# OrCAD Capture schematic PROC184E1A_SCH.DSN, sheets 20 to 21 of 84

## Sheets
20 20. SOC GENERAL & USB: size C; title: GENERAL IO; company: TEXAS INSTRUMENTS INCORPORATED; note: PROC184_SCH
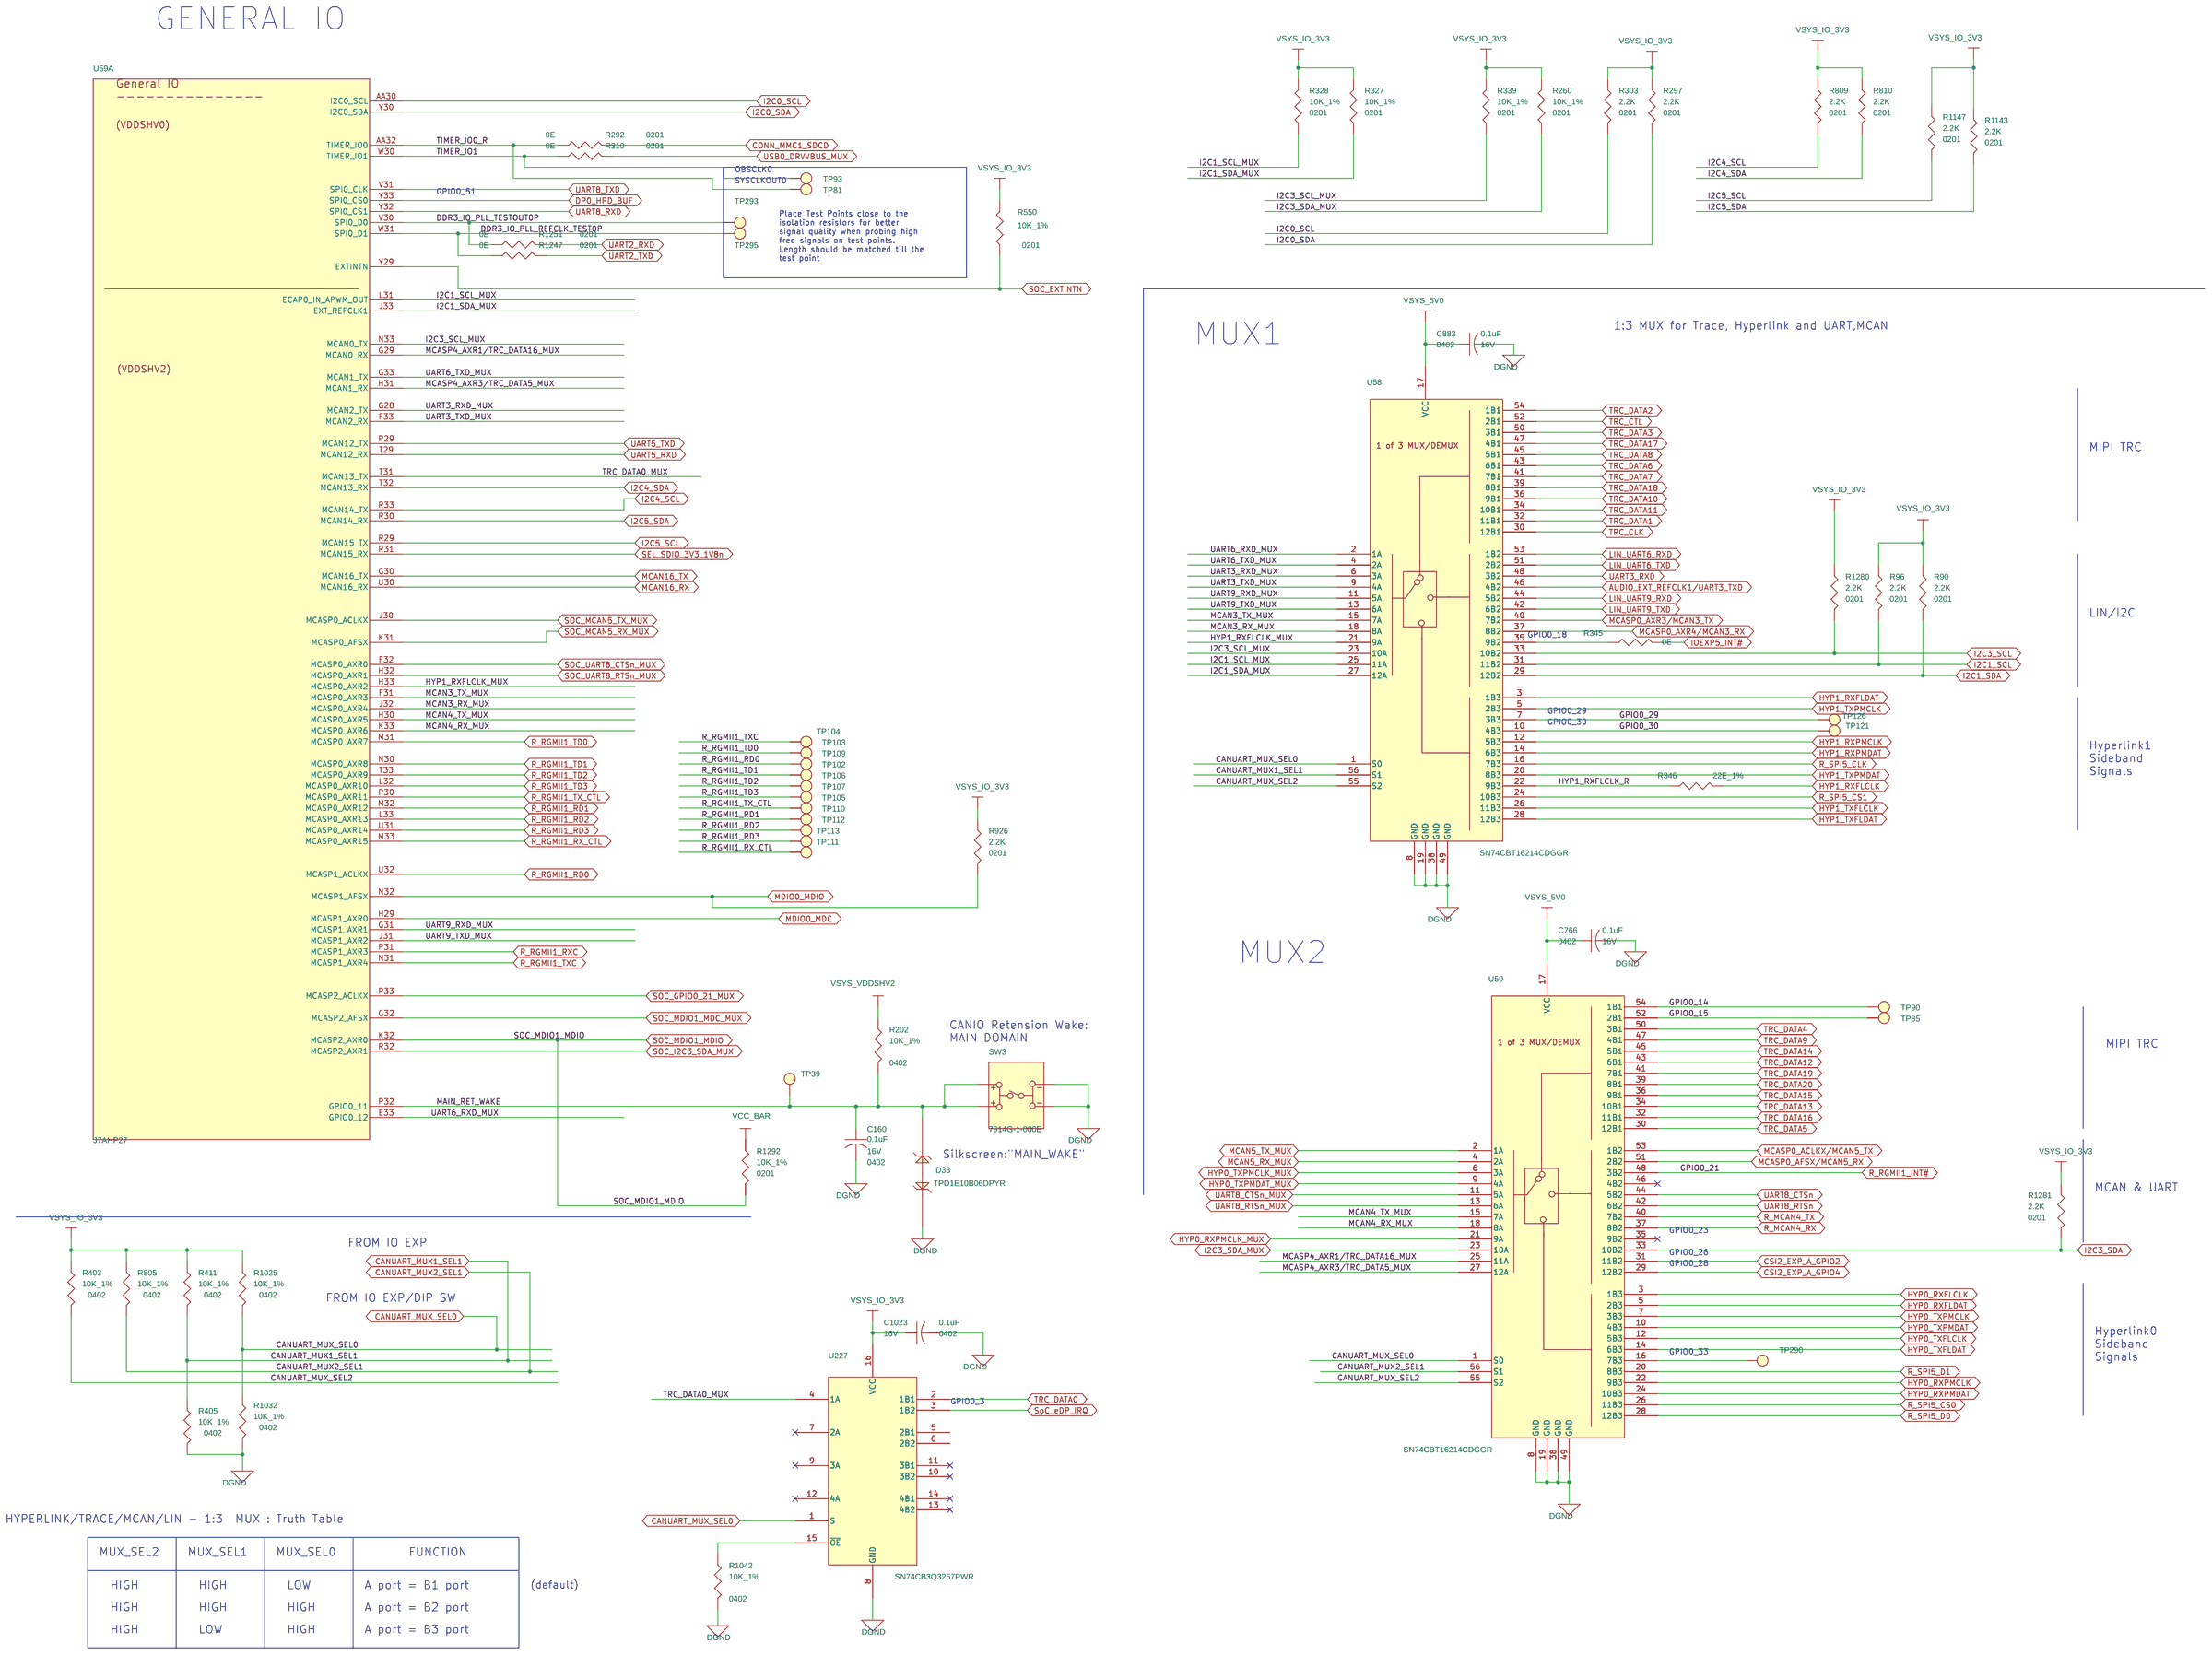
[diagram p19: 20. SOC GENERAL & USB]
21 21. SOC MCU & MMC & ADCs: size C; title: MCU RGMII & ADC; company: TEXAS INSTRUMENTS INCORPORATED; note: PROC184_SCH
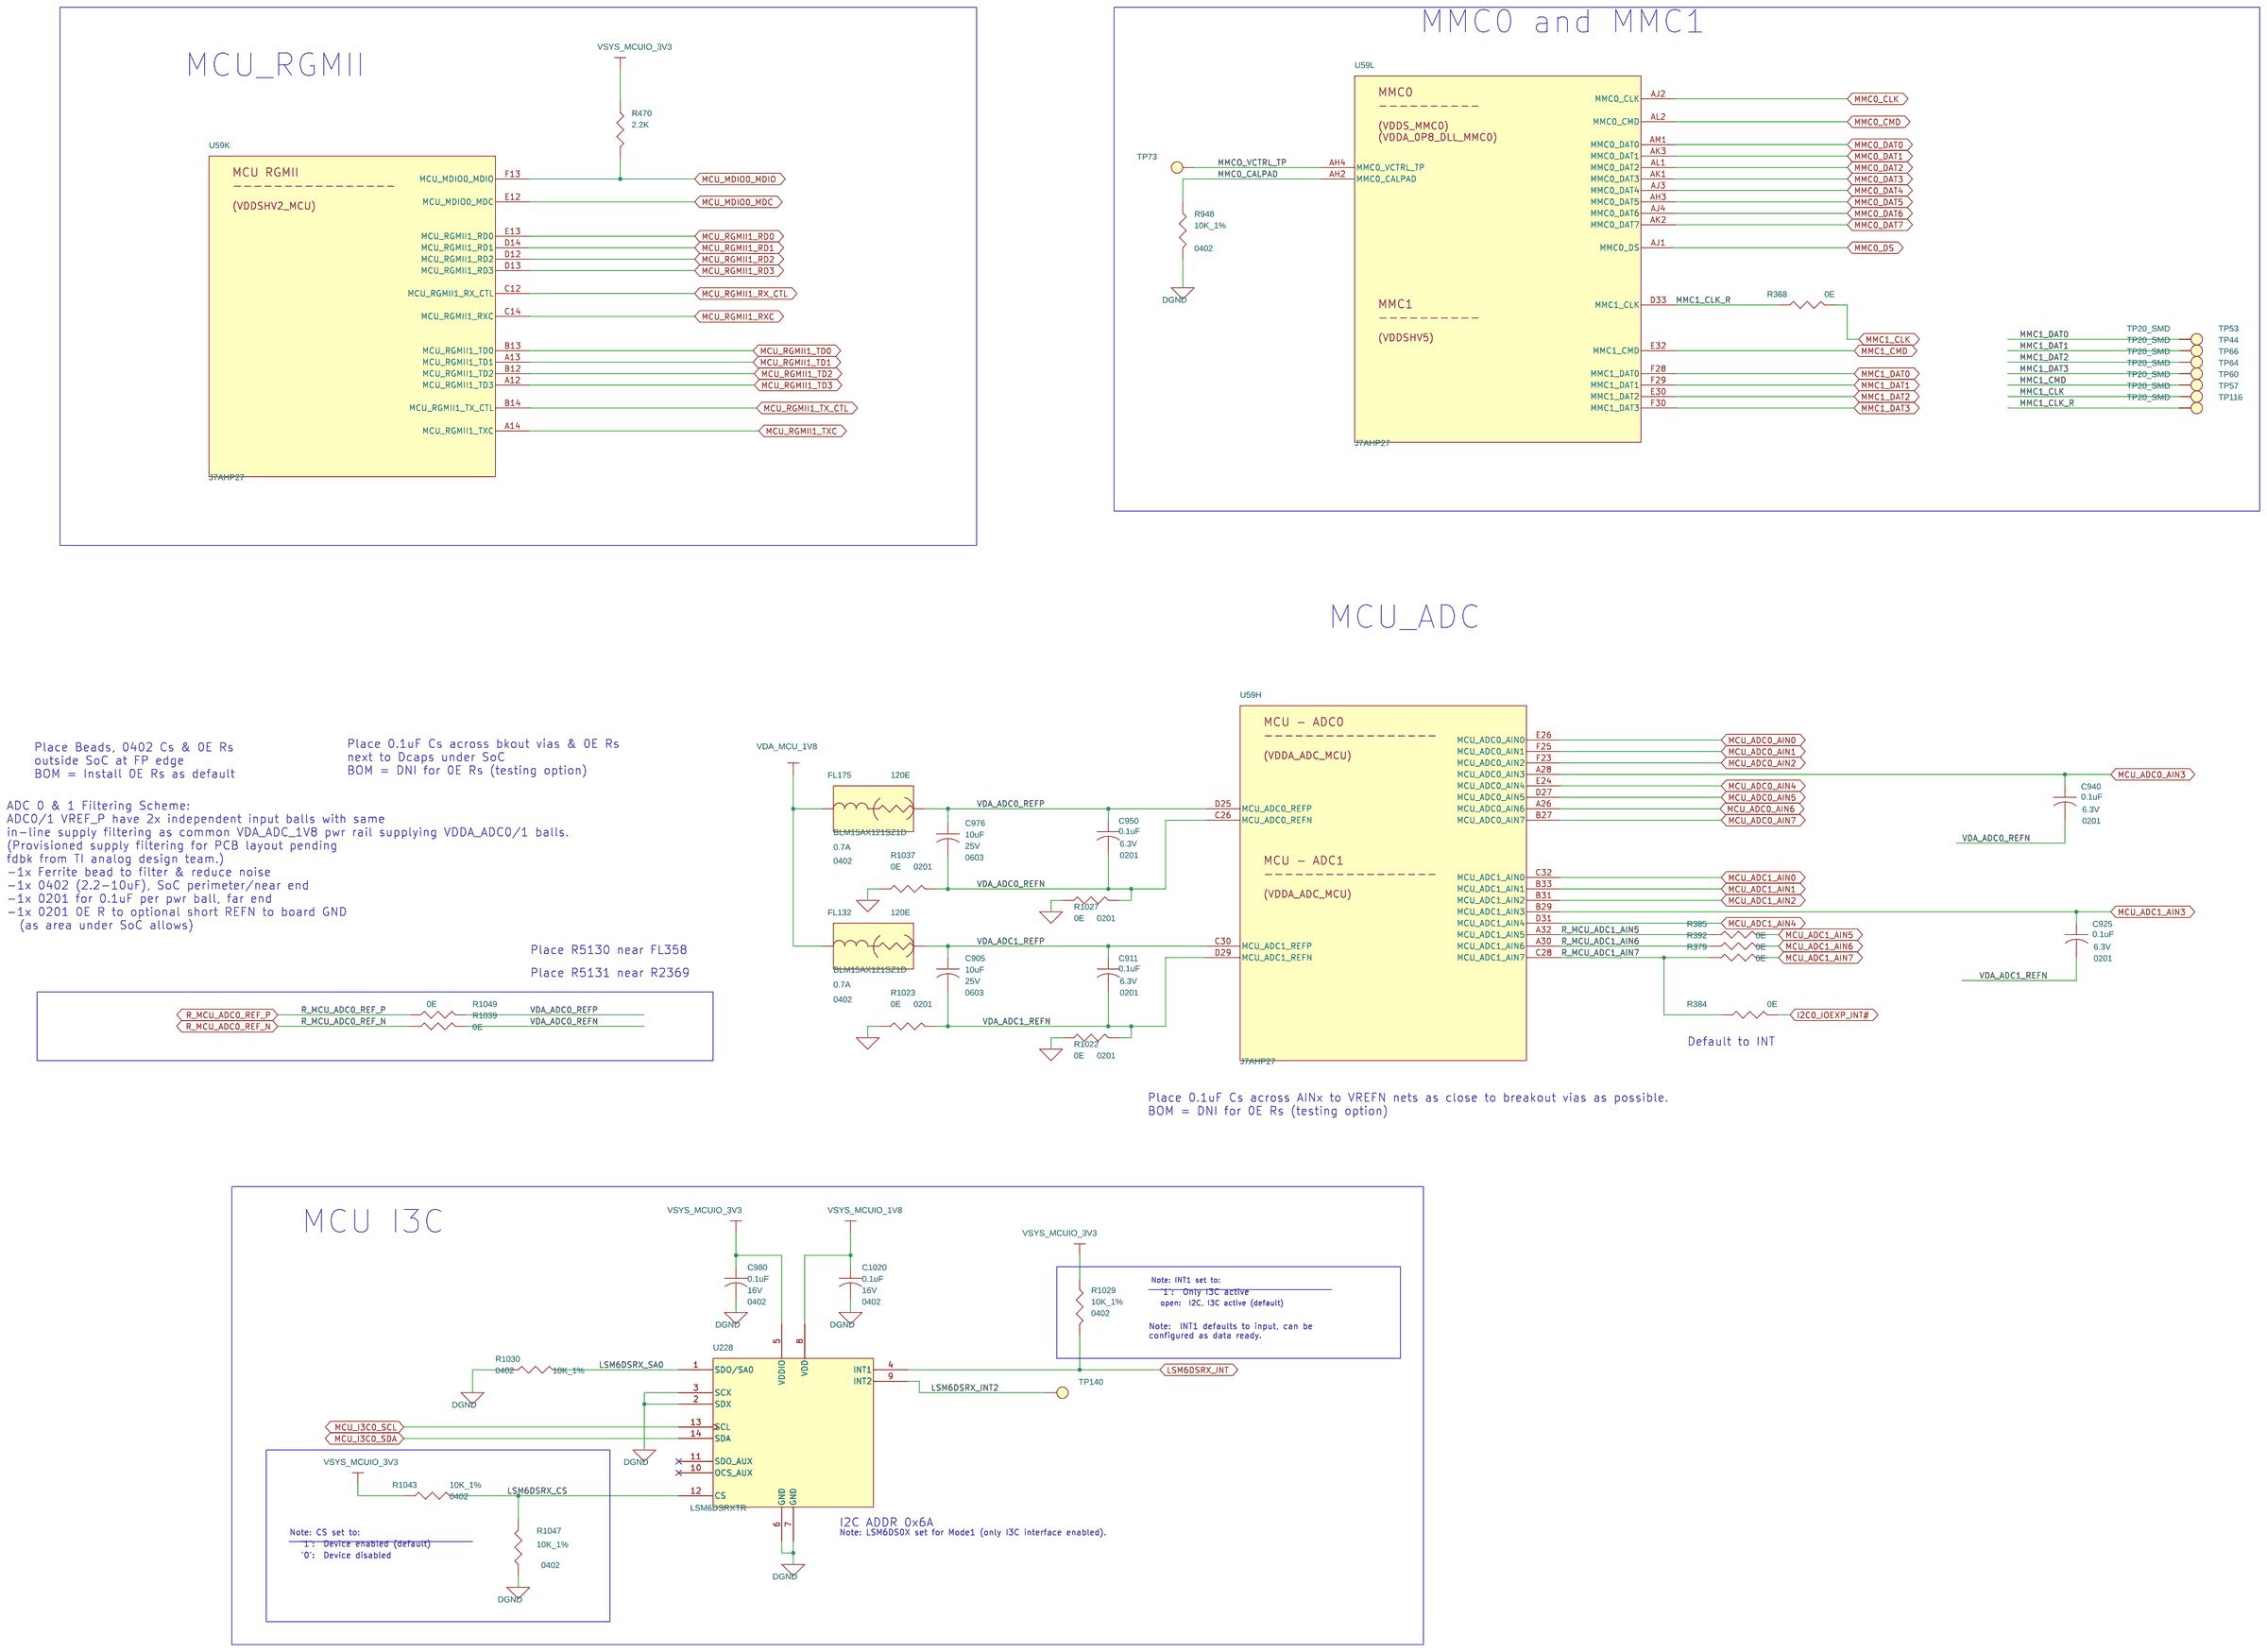
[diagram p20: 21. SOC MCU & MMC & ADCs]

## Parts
sheet 15. SOC EMIF1 & LPDDR4
U59  J7AHP27  [BGASKT-33X33-1063-P8MM]  (sections A,B,C,D,E,F,G,H,I,J,K,L,M,N,O,P,Q,R,S,T,U,V,W)
sheet 20. SOC GENERAL & USB
C160  0.1uF  [CAP0402_0-75]
C766  0.1uF  [CAP0402_0-75]
C883  0.1uF  [CAP0402_0-75]
C1023  0.1uF  [CAP0402_0-75]
D33  TPD1E10B06DPYR  [DIO_DFN0402_0-5]
R90  2.2K  [RES0201_0-5]
R96  2.2K  [RES0201_0-5]
R202  10K_1%  [RES0402_0-5]
R260  10K_1%  [RES0201_0-5]
R292  0E  [RES0201_0-5]
R297  2.2K  [RES0201_0-5]
R303  2.2K  [RES0201_0-5]
R310  0E  [RES0201_0-5]
R327  10K_1%  [RES0201_0-5]
R328  10K_1%  [RES0201_0-5]
R339  10K_1%  [RES0201_0-5]
R345  0E  [RES0201_0-5]
R346  22E_1%  [RES0402_0-5]
R403  10K_1%  [RES0402_0-5]
R405  10K_1%  [RES0402_0-5]
R411  10K_1%  [RES0402_0-5]
R550  10K_1%  [RES0201_0-5]
R805  10K_1%  [RES0402_0-5]
R809  2.2K  [RES0201_0-5]
R810  2.2K  [RES0201_0-5]
R926  2.2K  [RES0201_0-5]
R1025  10K_1%  [RES0402_0-5]
R1032  10K_1%  [RES0402_0-5]
R1042  10K_1%  [RES0402_0-5]
R1143  2.2K  [RES0201_0-5]
R1147  2.2K  [RES0201_0-5]
R1247  0E  [RES0201_0-5]
R1251  0E  [RES0201_0-5]
R1280  2.2K  [RES0201_0-5]
R1281  2.2K  [RES0201_0-5]
R1292  10K_1%  [RES0201_0-5]
SW3  7914G-1-000E  [SW4_100X216_200X200_SMD_4-2]
TP39  TP30_SMD  [TP30_SMD]
TP81  TP30_SMD  [TP30_SMD]
TP85  TP30_SMD  [TP30_SMD]
TP90  TP30_SMD  [TP30_SMD]
TP93  TP30_SMD  [TP30_SMD]
TP102  TP20_SMD  [TP20_SMD]
TP103  TP20_SMD  [TP20_SMD]
TP104  TP20_SMD  [TP20_SMD]
TP105  TP20_SMD  [TP20_SMD]
TP106  TP20_SMD  [TP20_SMD]
TP107  TP20_SMD  [TP20_SMD]
TP109  TP20_SMD  [TP20_SMD]
TP110  TP20_SMD  [TP20_SMD]
TP111  TP20_SMD  [TP20_SMD]
TP112  TP20_SMD  [TP20_SMD]
TP113  TP20_SMD  [TP20_SMD]
TP121  TP30_SMD  [TP30_SMD]
TP126  TP30_SMD  [TP30_SMD]
TP290  TP30_SMD  [TP30_SMD]
TP293  TP30_SMD  [TP30_SMD]
TP295  TP30_SMD  [TP30_SMD]
U50  SN74CBT16214CDGGR  [TSSOP56_19-68_560X240_1-2]
U58  SN74CBT16214CDGGR  [TSSOP56_19-68_560X240_1-2]
U227  SN74CB3Q3257PWR  [TSSOP16_25-59_205X180]
sheet 21. SOC MCU & MMC & ADCs
C905  10uF  [CAP0603_1-25]
C911  0.1uF  [CAP0201_0-5]
C925  0.1uF  [CAP0201_0-5]
C940  0.1uF  [CAP0201_0-5]
C950  0.1uF  [CAP0201_0-5]
C976  10uF  [CAP0603_1-25]
C980  0.1uF  [CAP0402_0-75]
C1020  0.1uF  [CAP0402_0-75]
FL132  120E  [EMIFIL_BLM15A_0402_0-6]
FL175  120E  [EMIFIL_BLM15A_0402_0-6]
R368  0E  [RES0402_0-5]
R379  0E  [RES0402_0-5]
R384  0E  [RES0402_0-5]
R385  0E  [RES0402_0-5]
R392  0E  [RES0402_0-5]
R470  2.2K  [RES0201_0-5]
R948  10K_1%  [RES0402_0-5]
R1022  0E  [RES0201_0-5]
R1023  0E  [RES0201_0-5]
R1027  0E  [RES0201_0-5]
R1029  10K_1%  [RES0402_0-5]
R1030  10K_1%  [RES0402_0-5]
R1037  0E  [RES0201_0-5]
R1039  0E  [RES0201_0-5]
R1043  10K_1%  [RES0402_0-5]
R1047  10K_1%  [RES0402_0-5]
R1049  0E  [RES0201_0-5]
TP44  TP20_SMD  [TP20_SMD]
TP53  TP20_SMD  [TP20_SMD]
TP57  TP20_SMD  [TP20_SMD]
TP60  TP20_SMD  [TP20_SMD]
TP64  TP20_SMD  [TP20_SMD]
TP66  TP20_SMD  [TP20_SMD]
TP73  TP30_SMD  [TP30_SMD]
TP116  TP20_SMD  [TP20_SMD]
TP140  TP30_SMD  [TP30_SMD]
U228  LSM6DSRXTR  [LGA14_19-68_120X100_0-9]

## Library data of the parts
U59 = J7AHP27SoC_BGA1063: IC J7AHP27 SoC EVM MICROPROCESSOR BGA1063; Chkd/date: PRADEEP/181223; Crtd /date: TAMILARASU/111223; Custom_Duty: 15%; Customs_HS_Code: 85423100; Distributor_name: NA; Distributor_part_number: NA; Footprint Path: Y:\MIS_DATABASE\Library\ALTIUM_TOOL\PCB_FOOTPRINTS\Altium_Footprint_Lib.PcbLib; Height: 3.30MM; Library Path: Y:\MIS_DATABASE\Library\ALTIUM_TOOL\SCHEMATICS_PARTS\MS_MICROPROCESSOR_Library.schlib; Mfr_name: NA; Mistral Part No: 141223120002; Package: BGA1063; Part_type: ICS\DIGITAL\MICROPROCESSOR; Project: J7AHP27_V08 SOC; RoHS: NA; Temperature: NA; Tolerance: NA; Voltage: NA; Wattage: NA; Weight: NA; Datasheet: Y:\MIS_DATABASE\DATASHEETS\ICS\DIGITAL\MICROCONTROLLER\J7AHP27.PDF
C160 C766 C883 C980 C1020 C1023 = CAP: CAP CERAMIC 0.1uF 16V 10% X7R AUTO 0402; Automotive Alternate_mfr_name: TDK; Automotive Alternate_mfr_part_number: CGA2B1X7R1C104K050BC; Chkd/date: NAVEED/021014; Crtd /date: VASANTHA/300514; Custom_Duty: 15%; Customs_HS_Code: 85322990; Direct Alternate_mfr_name: MURATA; Direct Alternate_mfr_part_number: GCM155R71C104JA55D; Distributor_name: DIGIKEY; Distributor_part_number: 490-4759-1-ND; Footprint Path: Y:\MIS_DATABASE\Library\ALTIUM_TOOL\PCB_FOOTPRINTS\Altium_Footprint_Lib.PcbLib; Height: 0.55MM; Library Path: Y:\MIS_DATABASE\Library\ALTIUM_TOOL\SCHEMATICS_PARTS\MS_DISCRETE_Library.schlib; Manufacturer: MURATA; Mfr_name: MURATA; Mfr_part_number: GCM155R71C104KA55D; Mistral Part No: 120016070006-R; Package: 0402; Part_type: CAPACITORS\CERAMIC; Project: DCMIST_FPGA_CARD; RoHS: RoHS; Temperature: -55°C+125°C; Tolerance: 10%; Voltage: 16V; Wattage: NA; Weight: 6mg; Datasheet: Y:\MIS_DATABASE\DATASHEETS\CAPACITORS\MURATA-GCM-SER.PDF
D33 = DIODE_SOD323: DIODE 1CH ESD PROTECTION X1SON2; Chkd/date: MANIRAJA/040420; Crtd /date: VASANTHA/181114; Custom_Duty: 15%; Customs_HS_Code: 85423100; Distributor_name: DIGIKEY; Distributor_part_number: 296-30406-1-ND; Footprint Path: Y:\MIS_DATABASE\Library\ALTIUM_TOOL\PCB_FOOTPRINTS\Altium_Footprint_Lib.PcbLib; Height: 0.45MM; Library Path: Y:\MIS_DATABASE\Library\ALTIUM_TOOL\SCHEMATICS_PARTS\MS_DISCRETE_Library.schlib; Manufacturer: TEXAS INSTRUMENTS; Mfr_name: TEXAS INSTRUMENTS; Mistral Part No: 130014110022-R; Package: X1SON2; Part_type: DIODE; Project: GALILEO_EVM; RoHS: RoHS; Temperature: -40°C+125°C; Tolerance: NA; Voltage: NA; Wattage: NA; Weight: 1mg; Datasheet: Y:\MIS_DATABASE\DATASHEETS\ICS\INTERFACE\TPD1E10B06-SER.PDF
R90 R96 R297 R303 R470 R809 R810 R926 R1143 R1147 R1280 R1281 = RESISTOR: RES 2.2K 1/20W 5% 0201; Chkd/date: MANIRAJA/050517; Crtd /date: MANIRAJA/050517; Custom_Duty: 15%; Customs_HS_Code: 85332119; Distributor_name: DIGIKEY; Distributor_part_number: 311-2.2KNCT-ND; Footprint Path: Y:\MIS_DATABASE\Library\ALTIUM_TOOL\PCB_FOOTPRINTS\Altium_Footprint_Lib.PcbLib; Height: 0.26MM; Library Path: Y:\MIS_DATABASE\Library\ALTIUM_TOOL\SCHEMATICS_PARTS\MS_DISCRETE_Library.schlib; Manufacturer: YAGEO AMERICA; Mfr_name: YAGEO AMERICA; Mfr_part_number: RC0201JR-072K2L; Mistral Part No: 110009030427-R; Package: 0201; Part_type: RESISTORS\FIXED; Project: GOLDEN-I LITE; RoHS: RoHS; Temperature: -55°C+125°C; Tolerance: 5%; Voltage: NA; Wattage: 1/20W; Weight: 0.17mg; Datasheet: Y:\MIS_DATABASE\DATASHEETS\RESISTORS\RCXXXXL-SER_MAR18.PDF
R202 = RESISTOR: RES 10K 1/16W 1% 0402; Assembly_Instruction: DNI; Chkd/date: VASANTHA/201216; Crtd /date: GEETHA/290506; Custom_Duty: 15%; Customs_HS_Code: 85332119; Distributor_name: DIGIKEY; Distributor_part_number: 311-10.0KLRTR-ND; Footprint Path: Y:\MIS_DATABASE\Library\ALTIUM_TOOL\PCB_FOOTPRINTS\Altium_Footprint_Lib.PcbLib; Height: 0.40MM; Library Path: Y:\MIS_DATABASE\Library\ALTIUM_TOOL\SCHEMATICS_PARTS\MS_DISCRETE_Library.schlib; Manufacturer: YAGEO AMERICA; Mfr_name: YAGEO AMERICA; Mfr_part_number: RC0402FR-0710KL; Mistral Part No: 110015090015-R; Package: 0402; Part_type: RESISTORS\FIXED; Project: VOCERA; RoHS: RoHS; Temperature: -55°C+155°C; Tolerance: 1%; Voltage: NA; Wattage: 1/16W; Weight: 0.65mg; Datasheet: Y:\MIS_DATABASE\DATASHEETS\RESISTORS\RCXXXXL-SER_MAR18.PDF
R260 R327 R328 R339 R550 = RESISTOR: RES 10K 1/20W 1% 0201; Chkd/date: MANIRAJA/080519; Crtd /date: ALVY/080519; Custom_Duty: 15%; Customs_HS_Code: 85332119; Distributor_name: DIGIKEY; Distributor_part_number: 1276-3670-1-ND; Footprint Path: Y:\MIS_DATABASE\Library\ALTIUM_TOOL\PCB_FOOTPRINTS\Altium_Footprint_Lib.PcbLib; Height: 0.26MM; Library Path: Y:\MIS_DATABASE\Library\ALTIUM_TOOL\SCHEMATICS_PARTS\MS_DISCRETE_Library.schlib; Manufacturer: SAMSUNG; Mfr_name: SAMSUNG; Mfr_part_number: RC0603F103CS; Mistral Part No: 110011040018-R; Package: 0201; Part_type: RESISTORS\FIXED; Project: BRUKER_SD820_COMMONDO; RoHS: RoHS; Temperature: -55°C+125°C; Tolerance: 1%; Voltage: NA; Wattage: 1/20W; Weight: 0.15mg; Datasheet: Y:\MIS_DATABASE\DATASHEETS\RESISTORS\SAMSUNG_RC-SER.PDF
R292 R310 R345 R1022 R1023 R1027 R1037 R1039 R1049 R1247 R1251 = RESISTOR: RES 0E 1/20W 5% 0201; Chkd/date: NAVEED/301214; Crtd /date: MUDDU/120710; Custom_Duty: 15%; Customs_HS_Code: 85332119; Distributor_name: DIGIKEY; Distributor_part_number: 311-0.0NCT-ND; Footprint Path: Y:\MIS_DATABASE\Library\ALTIUM_TOOL\PCB_FOOTPRINTS\Altium_Footprint_Lib.PcbLib; Height: 0.26MM; Library Path: Y:\MIS_DATABASE\Library\ALTIUM_TOOL\SCHEMATICS_PARTS\MS_DISCRETE_Library.schlib; Manufacturer: YAGEO AMERICA; Mfr_name: YAGEO AMERICA; Mfr_part_number: RC0201JR-070RL; Mistral Part No: 110010070067-R; Package: 0201; Part_type: RESISTORS\FIXED; Project: PB_BUGBASE; RoHS: RoHS; Temperature: -55°C+125°C; Tolerance: 5%; Voltage: NA; Wattage: 1/20W; Weight: 0.17mg; Datasheet: Y:\MIS_DATABASE\DATASHEETS\RESISTORS\RCXXXXL-SER_MAR18.PDF
R346 = RESISTOR: RES 22E 1/16W 1% 0402; Chkd/date: SUHAS/290910; Crtd /date: MAZHAR/090909; Cust_part_number: 4700-80047E; Custom_Duty: 15%; Customs_HS_Code: 85332119; Distributor_name: DIGIKEY; Distributor_part_number: 311-22.0LRCT-ND; Footprint Path: Y:\MIS_DATABASE\Library\ALTIUM_TOOL\PCB_FOOTPRINTS\Altium_Footprint_Lib.PcbLib; Height: 0.40MM; Library Path: Y:\MIS_DATABASE\Library\ALTIUM_TOOL\SCHEMATICS_PARTS\MS_DISCRETE_Library.schlib; Manufacturer: YAGEO AMERICA; Mfr_name: YAGEO AMERICA; Mfr_part_number: RC0402FR-0722RL; Mistral Part No: 110009090004-R; Package: 0402; Part_type: RESISTORS\FIXED; Project: VMEFMCD; RoHS: RoHS; Temperature: -55°C+155°C; Tolerance: 1%; Voltage: NA; Wattage: 1/16W; Weight: 0.65mg; Datasheet: Y:\MIS_DATABASE\DATASHEETS\RESISTORS\RCXXXXL-SER_MAR18.PDF
R403 R405 R411 R805 R948 R1025 R1029 R1030 R1032 R1042 R1043 R1047 = RESISTOR: RES 10K 1/16W 1% 0402; Chkd/date: VASANTHA/201216; Crtd /date: GEETHA/290506; Custom_Duty: 15%; Customs_HS_Code: 85332119; Distributor_name: DIGIKEY; Distributor_part_number: 311-10.0KLRTR-ND; Footprint Path: Y:\MIS_DATABASE\Library\ALTIUM_TOOL\PCB_FOOTPRINTS\Altium_Footprint_Lib.PcbLib; Height: 0.40MM; Library Path: Y:\MIS_DATABASE\Library\ALTIUM_TOOL\SCHEMATICS_PARTS\MS_DISCRETE_Library.schlib; Manufacturer: YAGEO AMERICA; Mfr_name: YAGEO AMERICA; Mfr_part_number: RC0402FR-0710KL; Mistral Part No: 110015090015-R; Package: 0402; Part_type: RESISTORS\FIXED; Project: VOCERA; RoHS: RoHS; Temperature: -55°C+155°C; Tolerance: 1%; Voltage: NA; Wattage: 1/16W; Weight: 0.65mg; Datasheet: Y:\MIS_DATABASE\DATASHEETS\RESISTORS\RCXXXXL-SER_MAR18.PDF
R1292 = RESISTOR: RES 10K 1/20W 1% 0201; Chkd/date: MANIRAJA/080519; Crtd /date: ALVY/080519; Custom_Duty: 15%; Customs_HS_Code: 85332119; Distributor_name: DIGIKEY; Distributor_part_number: 1276-3670-1-ND; Footprint Path: Y:\MIS_DATABASE\Library\ALTIUM_TOOL\PCB_FOOTPRINTS\Altium_Footprint_Lib.PcbLib; Height: 0.26MM; Library Path: Y:\MIS_DATABASE\Library\ALTIUM_TOOL\SCHEMATICS_PARTS\MS_DISCRETE_Library.schlib; Manufacturer: YAGEO AMERICA; Mfr_name: SAMSUNG; Mfr_part_number: RC0603F103CS; Mistral Part No: 110011040018-R; Package: 0201; Part_type: RESISTORS\FIXED; Project: BRUKER_SD820_COMMONDO; RoHS: RoHS; Temperature: -55°C+125°C; Tolerance: 1%; Voltage: NA; Wattage: 1/20W; Weight: 0.15mg; Datasheet: Y:\MIS_DATABASE\DATASHEETS\RESISTORS\SAMSUNG_RC-SER.PDF
SW3 = 7914G-1-000E__7914G: SWITCH SPST-NO 4MM SQ SMD 7914G; Chkd/date: VASANTHA/271216; Crtd /date: BAVISH/051010; Custom_Duty: 24%; Customs_HS_Code: 85369090; Distributor_name: DIGIKEY; Distributor_part_number: 7914G-000ECT-ND; Height: 4.19MM; Library Ref: 7914G-1-000E _7914G; Manufacturer: BOURNS; Mfr_name: BOURNS; Mistral Part No: 130015110004-R; Package: 7914G; Part_type: ELECTRO-MECHANICAL\SWITCH; Project: AAAUC; RoHS: RoHS; Temperature: -55°C+125°C; Tolerance: NA; Voltage: NA; Wattage: NA; Weight: NA; Datasheet: Y:\MIS_DATABASE\DATASHEETS\ICS\DIGITAL\COMBINATIONAL\7914G-1-000E.PDF
TP39 TP73 TP81 TP85 TP90 TP93 TP121 TP126 TP140 TP290 TP293 TP295 = TESTPOINT: TESTPOINT CIR 30 SMD; Chkd/date: SHREESHAIL/171006; Crtd /date: MAZHAR/171006; Custom_Duty: NA; Customs_HS_Code: NA; Distributor_name: NA; Distributor_part_number: NA; Footprint Path: Y:\MIS_DATABASE\Library\ALTIUM_TOOL\PCB_FOOTPRINTS\Altium_Footprint_Lib.PcbLib; Height: NA; Library Path: Y:\MIS_DATABASE\Library\ALTIUM_TOOL\SCHEMATICS_PARTS\MS_DISCRETE_Library.schlib; MECHANICAL 3D STEP FILE: NA; Manufacturer: LOCAL; Mfr_name: LOCAL; Mistral Part No: 130009030930; Package: SMD; Project: BT MODULE_CSRBC04; RoHS: NA; Temperature: NA; Tolerance: NA; Voltage: NA; Wattage: NA; Weight: NA; Datasheet: NA
TP44 TP53 TP57 TP60 TP64 TP66 TP102-TP107 TP109-TP113 TP116 = TESTPOINT: TESTPOINT CIR 20 SMD; Chkd/date: SHREESHAIL/171006; Crtd /date: MAZHAR/171006; Custom_Duty: NA; Customs_HS_Code: NA; Distributor_name: NA; Distributor_part_number: NA; Footprint Path: Y:\MIS_DATABASE\Library\ALTIUM_TOOL\PCB_FOOTPRINTS\Altium_Footprint_Lib.PcbLib; Height: NA; Library Path: Y:\MIS_DATABASE\Library\ALTIUM_TOOL\SCHEMATICS_PARTS\MS_DISCRETE_Library.schlib; MECHANICAL 3D STEP FILE: NA; Manufacturer: LOCAL; Mfr_name: LOCAL; Mistral Part No: NA; Package: SMD; Project: BT MODULE_CSRBC04; RoHS: NA; Temperature: NA; Tolerance: NA; Voltage: NA; Wattage: NA; Weight: NA; Datasheet: NA
U50 U58 = SN74CBT16214CDGGR_TSSOP56_TI: IC 12BIT 1-OF-3 FET MULTIPLEXER/DEMULTIPLEXER TSSOP56; Chkd/date: VASANTHA/110216; Crtd /date: VASANTHA/110216; Custom_Duty: 15%; Customs_HS_Code: 85423100; Distributor_name: DIGIKEY; Distributor_part_number: 296-19173-1-ND; Footprint Path: Y:\MIS_DATABASE\Library\ALTIUM_TOOL\PCB_FOOTPRINTS\Altium_Footprint_Lib.PcbLib; Height: 1.20MM; Library Path: Y:\MIS_DATABASE\Library\ALTIUM_TOOL\SCHEMATICS_PARTS\MS_COMBINATIONAL_Library.schlib; Library Ref: SN74CBT16214CDGGR_TSSOP56; Manufacturer: TEXAS INSTRUMENTS; Mfr_name: TEXAS INSTRUMENTS; Mistral Part No: 141016020009-R; Package: TSSOP56; Part_type: ICS\DIGITAL\COMBINATIONAL; Project: DM368_EVM; RoHS: RoHS; Temperature: -40°C+85°C; Tolerance: NA; Voltage: NA; Wattage: NA; Weight: NA; Datasheet: Y:\MIS_DATABASE\DATASHEETS\ICS\DIGITAL\COMBINATIONAL\SN74CBT16214CD.PDF
U227 = SN74CB3Q3257PWR_TSSOP16: IC 4BIT 1-OF-2 FET MULTIPLEXER/DEMULTIPLEXER TSSOP16; Chkd/date: SUHAS/251010; Crtd /date: USMAN/060109; Custom_Duty: 15%; Customs_HS_Code: 85423100; Distributor_name: DIGIKEY; Distributor_part_number: 296-19138-1-ND; Height: 1.20MM; Manufacturer: TEXAS INSTRUMENTS; Mfr_name: TEXAS INSTRUMENTS; Mistral Part No: 141009030117-R; Package: TSSOP16; Part_type: ICS\DIGITAL\COMBINATIONAL; Project: OMAP_EVM; RoHS: Sb/ Br FREE; Temperature: -40°C+85°C; Datasheet: Y:\MIS_DATABASE\DATASHEETS\ICS\DIGITAL\COMBINATIONAL\SN74CB3Q3257.PDF
C905 C976 = CAP: CAP CERAMIC 10uF 25V 20% X5R 0603; Automotive Alternate_mfr_name: MURATA; Automotive Alternate_mfr_part_number: GRT188C81C106ME13D; Chkd/date: MANIRAJA/040718; Crtd /date: MANIRAJA/040718; Custom_Duty: 15%; Customs_HS_Code: 85322990; Direct Alternate_mfr_name: SAMSUNG; Direct Alternate_mfr_part_number: CL10X106MO8NRNC; Distributor_name: DIGIKEY; Distributor_part_number: 490-10991-1-ND; Footprint Path: Y:\MIS_DATABASE\Library\ALTIUM_TOOL\PCB_FOOTPRINTS\Altium_Footprint_Lib.PcbLib; Height: 1.20MM; Library Path: Y:\MIS_DATABASE\Library\ALTIUM_TOOL\SCHEMATICS_PARTS\MS_DISCRETE_Library.schlib; Manufacturer: MURATA; Mfr_name: MURATA; Mfr_part_number: ZRB18AR61E106ME01L; Mistral Part No: 120018070001-R; Package: 0603; Part_type: CAPACITORS\CERAMIC; Project: CABS_VME_DIO; RoHS: RoHS; Temperature: -55°C+85°C; Tolerance: 20%; Voltage: 25V; Wattage: NA; Weight: 2mg; Datasheet: Y:\MIS_DATABASE\DATASHEETS\CAPACITORS\ZRB18AR61E106ME01L.PDF
C911 C925 C940 C950 = CAP: CAP CERAMIC 0.1uF 6.3V 10% X7S AUTO 0201; Assembly_Instruction: DNI; Chkd/date: MANIRAJA/011018; Crtd /date: MANIRAJA/011018; Custom_Duty: 15%; Customs_HS_Code: 85322990; Distributor_name: NA; Distributor_part_number: NA; Footprint Path: Y:\MIS_DATABASE\Library\ALTIUM_TOOL\PCB_FOOTPRINTS\Altium_Footprint_Lib.PcbLib; Height: 0.33MM; Library Path: Y:\MIS_DATABASE\Library\ALTIUM_TOOL\SCHEMATICS_PARTS\MS_DISCRETE_Library.schlib; Manufacturer: MURATA; Mfr_name: MURATA; Mfr_part_number: GCM033C70J104KE02D; Mistral Part No: 120018100001-R; Package: 0201; Part_type: CAPACITORS\CERAMIC; Project: TI_J7_SVB-DUT; RoHS: RoHS; Temperature: -55°C+125°C; Tolerance: 10%; Voltage: 6.3V; Wattage: NA; Weight: NA; Datasheet: Y:\MIS_DATABASE\DATASHEETS\CAPACITORS\MURATA-GCM-SER.PDF
FL132 FL175 = EMIFILTER_IND: IND FERRITE BEAD CHIP 120E 700mA 0402; Automotive Alternate_mfr_name: TDK; Automotive Alternate_mfr_part_number: MPZ1608S121ATDH5; Chkd/date: MANIRAJA/170122; Crtd /date: TAMILARASU/170122; Custom_Duty: 24%; Customs_HS_Code: 85437099; Direct Alternate_mfr_name: TDK; Direct Alternate_mfr_part_number: MPZ1608S121ATAH0; Distributor_name: DIGIKEY; Distributor_part_number: 490-16510-1-ND; Footprint Path: Y:\MIS_DATABASE\Library\ALTIUM_TOOL\PCB_FOOTPRINTS\Altium_Footprint_Lib.PcbLib; Height: 0.55MM; Library Path: Y:\MIS_DATABASE\Library\ALTIUM_TOOL\SCHEMATICS_PARTS\MS_FILTER_Library.schlib; Manufacturer: MURATA; Mfr_name: MURATA; Mfr_part_number: BLM15AX121SZ1D; Mistral Part No: 130022010017-R; Package: 0402; Part_type: INDUCTOR; Project: J7AHP_PROTO_BRD; RoHS: RoHS; SAT Current: 0.7A; Temperature: -55°C+125°C; Tolerance: 25%; Voltage: NA; Wattage: NA; Weight: 1mg; Datasheet: Y:\MIS_DATABASE\DATASHEETS\DISCRETES\INDUCTORS\BLM15-SZ1D-SER.PDF
R368 R379 R384 R385 R392 = RESISTOR: RES 0E 1/10W JUMPER 0402; Chkd/date: VASANTHA/061216; Crtd /date: NAVEED/201014; Custom_Duty: 15%; Customs_HS_Code: 85332119; Distributor_name: DIGIKEY; Distributor_part_number: P0.0JCT-ND; Footprint Path: Y:\MIS_DATABASE\Library\ALTIUM_TOOL\PCB_FOOTPRINTS\Altium_Footprint_Lib.PcbLib; Height: 0.40MM; IBISSP_MODLES: VALUE REPEATING 2 TIME; Library Path: Y:\MIS_DATABASE\Library\ALTIUM_TOOL\SCHEMATICS_PARTS\MS_DISCRETE_Library.schlib; Manufacturer: PANASONIC-ECG; Mfr_name: PANASONIC-ECG; Mfr_part_number: ERJ-2GE0R00X; Mistral Part No: 110018030052-R; Package: 0402; Part_type: RESISTORS\FIXED; Project: AEGIS POM; RoHS: RoHS; Temperature: -55°C+155°C; Tolerance: NA; Voltage: NA; Wattage: 1/10W; Weight: 0.8mg; Datasheet: Y:\MIS_DATABASE\DATASHEETS\RESISTORS\PAN-ERJSER_NOV17.PDF
U228 = MODULE_LSM6DSR: MODULE iNEMO INERTIAL ON 3D ACCELEROMETER AND 3D GYROSCOPE LGA14; Chkd/date: MANIRAJA/230920; Crtd /date: ALVY/230920; Custom_Duty: 15%; Customs_HS_Code: 85423100; Distributor_name: DIGIKEY; Distributor_part_number: 497-LSM6DSRXCT-ND; Footprint Path: Y:\MIS_DATABASE\Library\ALTIUM_TOOL\PCB_FOOTPRINTS\Altium_Footprint_Lib.PcbLib; Height: 0.86MM; Library Path: Y:\MIS_DATABASE\Library\ALTIUM_TOOL\SCHEMATICS_PARTS\MS_MODULE_Library.schlib; Manufacturer: ST MICROELECTRONICS; Mfr_name: ST MICROELECTRONICS; Mistral Part No: 180020090003-R; Package: LGA14; Part_type: MODULE; Project: J7VCL_SoM_PROC105E6; RoHS: RoHS; Temperature: -40°C+85°C; Tolerance: NA; Voltage: NA; Wattage: NA; Weight: 14mg; Datasheet: Y:\MIS_DATABASE\DATASHEETS\MISC\MODULES\LSM6DSRX.PDF

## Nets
DGND: C160.2 C766.2 C883.2 C980.2 C1020.2 C1023.2 D33.2 R405.2 R948.2 R1022.2 R1023.2 R1027.2 R1030.1 R1032.2 R1037.2 R1042.2 R1047.1 SW3.1 SW3.4 U50.8(GND) U50.19(GND) U50.38(GND) U50.49(GND) U58.8(GND) U58.19(GND) U58.38(GND) U58.49(GND) U227.8(GND) U228.2(SDX) U228.3(SCX) U228.6(GND) U228.7(GND) ; also on sheet 11 12 13 14 15 16 17 18 22 23 24 25 26 27 28 29 30 31 32 33 34 35 36 37 38 39 40 41 42 43 44 45 46 47 48 49 50 51 52 53 54 55 56 57 58 59 60 61 62 63 64 65 66 67 68 69 70 71 72 73 76 77 78 79 81 82 83 84
AUDIO_EXT_REFCLK1/UART3_TXD: U58.46(4B2) ; also on sheet 48
CANUART_MUX1_SEL1: R405.1 R411.2 U58.56(S1) ; also on sheet 38
CANUART_MUX2_SEL1: R805.2 U50.56(S1) ; also on sheet 38
CANUART_MUX_SEL0: R1025.2 R1032.1 U50.1(S0) U58.1(S0) U227.1(S) ; also on sheet 35 38
CANUART_MUX_SEL2: R403.2 U50.55(S2) U58.55(S2)
CONN_MMC1_SDCD: R292.1 ; also on sheet 40
CSI2_EXP_A_GPIO2: U50.31(11B2) ; also on sheet 31
CSI2_EXP_A_GPIO4: U50.29(12B2) ; also on sheet 31
DDR3_IO_PLL_REFCLK_TEST0P: R1247.2 TP295.1(TP) U59.W31(SPI0_D1)
DDR3_IO_PLL_TESTOUT0P: R1251.2 TP293.1(TP) U59.V30(SPI0_D0)
DP0_HPD_BUF: U59.Y33(SPI0_CS0) ; also on sheet 57
GPIO0_14: TP90.1(TP) U50.54(1B1)
GPIO0_15: TP85.1(TP) U50.52(2B1)
GPIO0_29: TP126.1(TP) U58.7(3B3)
GPIO0_30: TP121.1(TP) U58.10(4B3)
HYP0_RXFLCLK: U50.3(1B3) ; also on sheet 19
HYP0_RXFLDAT: U50.5(2B3) ; also on sheet 19
HYP0_RXPMCLK: U50.22(9B3) ; also on sheet 19
HYP0_RXPMCLK_MUX: U50.21(9A) ; also on sheet 19
HYP0_RXPMDAT: U50.24(10B3) ; also on sheet 19
HYP0_TXFLCLK: U50.12(5B3) ; also on sheet 19
HYP0_TXFLDAT: U50.14(6B3) ; also on sheet 19
HYP0_TXPMCLK: U50.7(3B3) ; also on sheet 19
HYP0_TXPMCLK_MUX: U50.6(3A) ; also on sheet 19
HYP0_TXPMDAT: U50.10(4B3) ; also on sheet 19
HYP0_TXPMDAT_MUX: U50.9(4A) ; also on sheet 19
HYP1_RXFLCLK: R346.2 ; also on sheet 29
HYP1_RXFLCLK_MUX: U58.21(9A) U59.H33(MCASP0_AXR2)
HYP1_RXFLCLK_R: R346.1 U58.22(9B3)
HYP1_RXFLDAT: U58.3(1B3) ; also on sheet 29
HYP1_RXPMCLK: U58.12(5B3) ; also on sheet 29
HYP1_RXPMDAT: U58.14(6B3) ; also on sheet 29
HYP1_TXFLCLK: U58.26(11B3) ; also on sheet 29
HYP1_TXFLDAT: U58.28(12B3) ; also on sheet 29
HYP1_TXPMCLK: U58.5(2B3) ; also on sheet 29
HYP1_TXPMDAT: U58.20(8B3) ; also on sheet 29
I2C0_IOEXP_INT#: R384.2 ; also on sheet 38
I2C0_SCL: R303.2 U59.AA30(I2C0_SCL) ; also on sheet 32 33 34 38 58 59
I2C0_SDA: R297.2 U59.Y30(I2C0_SDA) ; also on sheet 32 33 34 38 58 59
I2C1_SCL: R96.2 U58.31(11B2) ; also on sheet 63
I2C1_SCL_MUX: R328.1 U58.25(11A) U59.L31(ECAP0_IN_APWM_OUT)
I2C1_SDA: R90.2 U58.29(12B2) ; also on sheet 63
I2C1_SDA_MUX: R327.1 U58.27(12A) U59.J33(EXT_REFCLK1)
I2C3_SCL: R1280.2 U58.33(10B2) ; also on sheet 38 82
I2C3_SCL_MUX: R339.1 U58.23(10A) U59.N33(MCAN0_TX)
I2C3_SDA: R1281.2 U50.33(10B2) ; also on sheet 38 82
I2C3_SDA_MUX: R260.1 U50.23(10A) ; also on sheet 19
I2C4_SCL: R809.2 U59.R33(MCAN14_TX) ; also on sheet 38 61
I2C4_SDA: R810.2 U59.T32(MCAN13_RX) ; also on sheet 38 61
I2C5_SCL: R1147.2 U59.R29(MCAN15_TX) ; also on sheet 31 38
I2C5_SDA: R1143.2 U59.R30(MCAN14_RX) ; also on sheet 31 38
IOEXP5_INT#: R345.1 ; also on sheet 38
LIN_UART6_RXD: U58.53(1B2) ; also on sheet 19
LIN_UART6_TXD: U58.51(2B2) ; also on sheet 19
LIN_UART9_RXD: U58.44(5B2) ; also on sheet 19
LIN_UART9_TXD: U58.42(6B2) ; also on sheet 19
LSM6DSRX_CS: R1043.2 R1047.2 U228.12(CS)
LSM6DSRX_INT: R1029.2 U228.4(INT1) ; also on sheet 18
LSM6DSRX_INT2: TP140.1(TP) U228.9(INT2)
LSM6DSRX_SA0: R1030.2 U228.1(SDO/SA0)
MAIN_RET_WAKE: C160.1 D33.1 R202.2 SW3.2 SW3.3 TP39.1(TP) U59.P32(GPIO0_11)
MCAN3_RX_MUX: U58.18(8A) U59.J32(MCASP0_AXR4)
MCAN3_TX_MUX: U58.15(7A) U59.F31(MCASP0_AXR3)
MCAN4_RX_MUX: U50.18(8A) U59.K33(MCASP0_AXR6)
MCAN4_TX_MUX: U50.15(7A) U59.H30(MCASP0_AXR5)
MCAN5_RX_MUX: U50.4(2A) ; also on sheet 19
MCAN5_TX_MUX: U50.2(1A) ; also on sheet 19
MCAN16_RX: U59.U30(MCAN16_RX) ; also on sheet 81
MCAN16_TX: U59.G30(MCAN16_TX) ; also on sheet 81
MCASP0_ACLKX/MCAN5_TX: U50.53(1B2) ; also on sheet 48
MCASP0_AFSX/MCAN5_RX: U50.51(2B2) ; also on sheet 48
MCASP0_AXR3/MCAN3_TX: U58.40(7B2) ; also on sheet 48
MCASP0_AXR4/MCAN3_RX: U58.37(8B2) ; also on sheet 48
MCASP4_AXR1/TRC_DATA16_MUX: U50.25(11A) U59.G29(MCAN0_RX)
MCASP4_AXR3/TRC_DATA5_MUX: U50.27(12A) U59.H31(MCAN1_RX)
MCU_ADC0_AIN0: U59.E26(MCU_ADC0_AIN0) ; also on sheet 58
MCU_ADC0_AIN1: U59.F25(MCU_ADC0_AIN1) ; also on sheet 58
MCU_ADC0_AIN2: U59.F23(MCU_ADC0_AIN2) ; also on sheet 58
MCU_ADC0_AIN3: C940.1 U59.A28(MCU_ADC0_AIN3) ; also on sheet 58
MCU_ADC0_AIN4: U59.E24(MCU_ADC0_AIN4) ; also on sheet 58
MCU_ADC0_AIN5: U59.D27(MCU_ADC0_AIN5) ; also on sheet 58
MCU_ADC0_AIN6: U59.A26(MCU_ADC0_AIN6) ; also on sheet 58
MCU_ADC0_AIN7: U59.B27(MCU_ADC0_AIN7) ; also on sheet 58
MCU_ADC1_AIN0: U59.C32(MCU_ADC1_AIN0) ; also on sheet 30 58
MCU_ADC1_AIN1: U59.B33(MCU_ADC1_AIN1) ; also on sheet 30 58
MCU_ADC1_AIN2: U59.B31(MCU_ADC1_AIN2) ; also on sheet 30
MCU_ADC1_AIN3: C925.1 U59.B29(MCU_ADC1_AIN3) ; also on sheet 30
MCU_ADC1_AIN4: U59.D31(MCU_ADC1_AIN4) ; also on sheet 30
MCU_ADC1_AIN5: R385.2 ; also on sheet 30
MCU_ADC1_AIN6: R392.2 ; also on sheet 30
MCU_ADC1_AIN7: R379.2 ; also on sheet 30
MCU_I3C0_SCL: U228.13(SCL) ; also on sheet 18 58
MCU_I3C0_SDA: U228.14(SDA) ; also on sheet 18 58
MCU_MDIO0_MDC: U59.E12(MCU_MDIO0_MDC) ; also on sheet 55
MCU_MDIO0_MDIO: R470.2 U59.F13(MCU_MDIO0_MDIO) ; also on sheet 55
MCU_RGMII1_RD0: U59.E13(MCU_RGMII1_RD0) ; also on sheet 55
MCU_RGMII1_RD1: U59.D14(MCU_RGMII1_RD1) ; also on sheet 55
MCU_RGMII1_RD2: U59.D12(MCU_RGMII1_RD2) ; also on sheet 55
MCU_RGMII1_RD3: U59.D13(MCU_RGMII1_RD3) ; also on sheet 55
MCU_RGMII1_RX_CTL: U59.C12(MCU_RGMII1_RX_CTL) ; also on sheet 55
MCU_RGMII1_RXC: U59.C14(MCU_RGMII1_RXC) ; also on sheet 55
MCU_RGMII1_TD0: U59.B13(MCU_RGMII1_TD0) ; also on sheet 55
MCU_RGMII1_TD1: U59.A13(MCU_RGMII1_TD1) ; also on sheet 55
MCU_RGMII1_TD2: U59.B12(MCU_RGMII1_TD2) ; also on sheet 55
MCU_RGMII1_TD3: U59.A12(MCU_RGMII1_TD3) ; also on sheet 55
MCU_RGMII1_TX_CTL: U59.B14(MCU_RGMII1_TX_CTL) ; also on sheet 55
MCU_RGMII1_TXC: U59.A14(MCU_RGMII1_TXC) ; also on sheet 55
MDIO0_MDC: U59.H29(MCASP1_AXR0) ; also on sheet 19
MDIO0_MDIO: R926.2 U59.N32(MCASP1_AFSX) ; also on sheet 19
MMC0_CALPAD: R948.1 U59.AH2(MMC0_CALPAD)
MMC0_CLK: U59.AJ2(MMC0_CLK) ; also on sheet 41
MMC0_CMD: U59.AL2(MMC0_CMD) ; also on sheet 41
MMC0_DAT0: U59.AM1(MMC0_DAT0) ; also on sheet 41
MMC0_DAT1: U59.AK3(MMC0_DAT1) ; also on sheet 41
MMC0_DAT2: U59.AL1(MMC0_DAT2) ; also on sheet 41
MMC0_DAT3: U59.AK1(MMC0_DAT3) ; also on sheet 41
MMC0_DAT4: U59.AJ3(MMC0_DAT4) ; also on sheet 41
MMC0_DAT5: U59.AH3(MMC0_DAT5) ; also on sheet 41
MMC0_DAT6: U59.AJ4(MMC0_DAT6) ; also on sheet 41
MMC0_DAT7: U59.AK2(MMC0_DAT7) ; also on sheet 41
MMC0_DS: U59.AJ1(MMC0_DS) ; also on sheet 41
MMC1_CLK: R368.2 TP57.1(TP) ; also on sheet 40
MMC1_CLK_R: R368.1 TP116.1(TP) U59.D33(MMC1_CLK)
MMC1_CMD: TP60.1(TP) U59.E32(MMC1_CMD) ; also on sheet 40
MMC1_DAT0: TP53.1(TP) U59.F28(MMC1_DAT0) ; also on sheet 40
MMC1_DAT1: TP44.1(TP) U59.F29(MMC1_DAT1) ; also on sheet 40
MMC1_DAT2: TP66.1(TP) U59.E30(MMC1_DAT2) ; also on sheet 40
MMC1_DAT3: TP64.1(TP) U59.F30(MMC1_DAT3) ; also on sheet 40
MMCO_VCTRL_TP: TP73.1(TP) U59.AH4(MMC0_VCTRL_TP)
R_MCAN4_RX: U50.37(8B2) ; also on sheet 19
R_MCAN4_TX: U50.40(7B2) ; also on sheet 19
R_MCU_ADC0_REF_N: R1039.2 ; also on sheet 58
R_MCU_ADC0_REF_P: R1049.2 ; also on sheet 58
R_MCU_ADC1_AIN5: R385.1 U59.A32(MCU_ADC1_AIN5)
R_MCU_ADC1_AIN6: R392.1 U59.A30(MCU_ADC1_AIN6)
R_MCU_ADC1_AIN7: R379.1 R384.1 U59.C28(MCU_ADC1_AIN7)
R_RGMII1_INT#: U50.48(3B2) ; also on sheet 19
R_RGMII1_RD0: TP109.1(TP) U59.U32(MCASP1_ACLKX) ; also on sheet 19
R_RGMII1_RD1: TP110.1(TP) U59.M32(MCASP0_AXR12) ; also on sheet 19
R_RGMII1_RD2: TP112.1(TP) U59.L33(MCASP0_AXR13) ; also on sheet 19
R_RGMII1_RD3: TP113.1(TP) U59.U31(MCASP0_AXR14) ; also on sheet 19
R_RGMII1_RX_CTL: TP111.1(TP) U59.M33(MCASP0_AXR15) ; also on sheet 19
R_RGMII1_RXC: U59.P31(MCASP1_AXR3) ; also on sheet 19
R_RGMII1_TD0: TP103.1(TP) U59.M31(MCASP0_AXR7) ; also on sheet 19
R_RGMII1_TD1: TP102.1(TP) U59.N30(MCASP0_AXR8) ; also on sheet 19
R_RGMII1_TD2: TP106.1(TP) U59.T33(MCASP0_AXR9) ; also on sheet 19
R_RGMII1_TD3: TP107.1(TP) U59.L32(MCASP0_AXR10) ; also on sheet 19
R_RGMII1_TX_CTL: TP105.1(TP) U59.P30(MCASP0_AXR11) ; also on sheet 19
R_RGMII1_TXC: TP104.1(TP) U59.N31(MCASP1_AXR4) ; also on sheet 19
R_SPI5_CLK: U58.16(7B3) ; also on sheet 19
R_SPI5_CS0: U50.26(11B3) ; also on sheet 19
R_SPI5_CS1: U58.24(10B3) ; also on sheet 19
R_SPI5_D0: U50.28(12B3) ; also on sheet 19
R_SPI5_D1: U50.20(8B3) ; also on sheet 19
SEL_SDIO_3V3_1V8n: U59.R31(MCAN15_RX) ; also on sheet 72
SoC_eDP_IRQ: U227.3(1B2) ; also on sheet 61
SOC_EXTINTN: R550.1 U59.Y29(EXTINTN) ; also on sheet 35
SOC_GPIO0_21_MUX: U59.P33(MCASP2_ACLKX) ; also on sheet 19
SOC_I2C3_SDA_MUX: U59.R32(MCASP2_AXR1) ; also on sheet 19
SOC_MCAN5_RX_MUX: U59.K31(MCASP0_AFSX) ; also on sheet 19
SOC_MCAN5_TX_MUX: U59.J30(MCASP0_ACLKX) ; also on sheet 19
SOC_MDIO1_MDC_MUX: U59.G32(MCASP2_AFSX) ; also on sheet 19
SOC_MDIO1_MDIO: R1292.2 U59.K32(MCASP2_AXR0) ; also on sheet 19
SOC_UART8_CTSn_MUX: U59.F32(MCASP0_AXR0) ; also on sheet 19
SOC_UART8_RTSn_MUX: U59.H32(MCASP0_AXR1) ; also on sheet 19
TIMER_IO0_R: R292.2 TP81.1(TP) U59.AA32(TIMER_IO0)
TIMER_IO1: R310.2 TP93.1(TP) U59.W30(TIMER_IO1)
TRC_CLK: U58.30(12B1) ; also on sheet 48
TRC_CTL: U58.52(2B1) ; also on sheet 48
TRC_DATA0: U227.2(1B1) ; also on sheet 48
TRC_DATA0_MUX: U59.T31(MCAN13_TX) U227.4(1A)
TRC_DATA1: U58.32(11B1) ; also on sheet 48
TRC_DATA2: U58.54(1B1) ; also on sheet 48
TRC_DATA3: U58.50(3B1) ; also on sheet 48
TRC_DATA4: U50.50(3B1) ; also on sheet 48
TRC_DATA5: U50.30(12B1) ; also on sheet 48
TRC_DATA6: U58.43(6B1) ; also on sheet 48
TRC_DATA7: U58.41(7B1) ; also on sheet 48
TRC_DATA8: U58.45(5B1) ; also on sheet 48
TRC_DATA9: U50.47(4B1) ; also on sheet 48
TRC_DATA10: U58.36(9B1) ; also on sheet 48
TRC_DATA11: U58.34(10B1) ; also on sheet 48
TRC_DATA12: U50.43(6B1) ; also on sheet 48
TRC_DATA13: U50.34(10B1) ; also on sheet 48
TRC_DATA14: U50.45(5B1) ; also on sheet 48
TRC_DATA15: U50.36(9B1) ; also on sheet 48
TRC_DATA16: U50.32(11B1) ; also on sheet 48
TRC_DATA17: U58.47(4B1) ; also on sheet 48
TRC_DATA18: U58.39(8B1) ; also on sheet 48
TRC_DATA19: U50.41(7B1) ; also on sheet 48
TRC_DATA20: U50.39(8B1) ; also on sheet 48
UART2_RXD: R1251.1 ; also on sheet 45
UART2_TXD: R1247.1 ; also on sheet 45
UART3_RXD: U58.48(3B2) ; also on sheet 45
UART3_RXD_MUX: U58.6(3A) U59.G28(MCAN2_TX)
UART3_TXD_MUX: U58.9(4A) U59.F33(MCAN2_RX)
UART5_RXD: U59.T29(MCAN12_RX) ; also on sheet 45
UART5_TXD: U59.P29(MCAN12_TX) ; also on sheet 45
UART6_RXD_MUX: U58.2(1A) U59.E33(GPIO0_12)
UART6_TXD_MUX: U58.4(2A) U59.G33(MCAN1_TX)
UART8_CTSn: U50.44(5B2) ; also on sheet 45
UART8_CTSn_MUX: U50.11(5A) ; also on sheet 19
UART8_RTSn: U50.42(6B2) ; also on sheet 45
UART8_RTSn_MUX: U50.13(6A) ; also on sheet 19
UART8_RXD: U59.Y32(SPI0_CS1) ; also on sheet 45
UART8_TXD: U59.V31(SPI0_CLK) ; also on sheet 45
UART9_RXD_MUX: U58.11(5A) U59.G31(MCASP1_AXR1)
UART9_TXD_MUX: U58.13(6A) U59.J31(MCASP1_AXR2)
USB0_DRVVBUS_MUX: R310.1 ; also on sheet 24
VDA_ADC0_REFN: C940.2 C950.2 C976.2 R1027.1 R1037.1 R1039.1 U59.C26(MCU_ADC0_REFN)
VDA_ADC0_REFP: C950.1 C976.1 FL175.2 R1049.1 U59.D25(MCU_ADC0_REFP)
VDA_ADC1_REFN: C905.2 C911.2 C925.2 R1022.1 R1023.1 U59.D29(MCU_ADC1_REFN)
VDA_ADC1_REFP: C905.1 C911.1 FL132.2 U59.C30(MCU_ADC1_REFP)
VDA_MCU_1V8: FL132.1 FL175.1 ; also on sheet 25 36 69 74
VSYS_5V0: C766.1 C883.1 U50.17(VCC) U58.17(VCC) ; also on sheet 30 31 50 52 59 65 68 72 81 82 83 84
VSYS_IO_3V3: C1023.1 R90.1 R96.1 R260.2 R297.1 R303.1 R327.2 R328.2 R339.2 R403.1 R411.1 R550.2 R805.1 R809.1 R810.1 R926.1 R1025.1 R1143.1 R1147.1 R1280.1 R1281.1 R1292.1 U227.16(VCC) ; also on sheet 18 22 24 29 30 31 32 33 35 36 37 38 40 41 42 43 45 46 48 50 51 53 56 57 58 59 60 61 65 66 68 75 81 82
VSYS_MCUIO_1V8: C1020.1 U228.8(VDD) ; also on sheet 17 37 39 53 62 65 75
VSYS_MCUIO_3V3: C980.1 R470.1 R1029.1 R1043.1 U228.5(VDDIO) ; also on sheet 16 17 18 22 23 35 36 43 44 48 49 55 62 65 68 75
VSYS_VDDSHV2: R202.1 ; also on sheet 18 81
N33187905: R1042.1 U227.15(~{OE})
N33189610: R345.2 U58.35(9B2)
N33190088: TP290.1(TP) U50.16(7B3)

Not connected (* = marked no-connect by the designer): U50 35(9B2)* 46(4B2)*; U227 5(2B1) 6(2B2) 7(2A)* 9(3A)* 10(3B2)* 11(3B1)* 12(4A)* 13(4B2)* 14(4B1)*; U228 10(OCS_AUX)* 11(SDO_AUX)*

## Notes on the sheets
sheet 20
- GENERAL IO
- OBSCLK0
- GPIO0_51
- SYSCLKOUT0
- Place Test Points close to the
  isolation resistors for better
  signal quality when probing high
  freq signals on test points.
  Length should be matched till the
  test point
- MUX1
- 1:3 MUX for Trace, Hyperlink and UART,MCAN
- MIPI TRC
- LIN/I2C
- GPIO0_18
- GPIO0_29
- GPIO0_30
- Hyperlink1
  Sideband
  Signals
- MUX2
- CANIO Retension Wake:
  MAIN DOMAIN
- MIPI TRC
- Silkscreen:"MAIN_WAKE"
- MCAN & UART
- GPIO0_23
- FROM IO EXP
- GPIO0_26
- GPIO0_28
- FROM IO EXP/DIP SW
- Hyperlink0
  Sideband
  Signals
- GPIO0_33
- GPIO0_3
- HYPERLINK/TRACE/MCAN/LIN - 1:3  MUX : Truth Table
- MUX_SEL2
- MUX_SEL1
- MUX_SEL0
- FUNCTION
- HIGH
- HIGH
- LOW
- A port = B1 port
- (default)
- HIGH
- HIGH
- HIGH
- A port = B2 port
- HIGH
- LOW
- HIGH
- A port = B3 port
sheet 21
- MMC0 and MMC1
- MCU_RGMII
- MCU_ADC
- Place 0.1uF Cs across bkout vias & 0E Rs
  next to Dcaps under SoC
  BOM = DNI for 0E Rs (testing option)
- Place Beads, 0402 Cs & 0E Rs
  outside SoC at FP edge
  BOM = Install 0E Rs as default
- ADC 0 & 1 Filtering Scheme:
  ADC0/1 VREF_P have 2x independent input balls with same
  in-line supply filtering as common VDA_ADC_1V8 pwr rail supplying VDDA_ADC0/1 balls.
  (Provisioned supply filtering for PCB layout pending
  fdbk from TI analog design team.)
  -1x Ferrite bead to filter & reduce noise
  -1x 0402 (2.2-10uF), SoC perimeter/near end
  -1x 0201 for 0.1uF per pwr ball, far end
  -1x 0201 0E R to optional short REFN to board GND
    (as area under SoC allows)
- Place R5130 near FL358
- Place R5131 near R2369
- Default to INT
- Place 0.1uF Cs across AINx to VREFN nets as close to breakout vias as possible.
  BOM = DNI for 0E Rs (testing option)
- MCU I3C
- Note: INT1 set to:
- '1':  Only I3C active
- open:  I2C, I3C active (default)
- Note:  INT1 defaults to input, can be
  configured as data ready.
- I2C ADDR 0x6A
- Note: CS set to:
- Note: LSM6DS0X set for Mode1 (only I3C interface enabled).
- '0':  Device disabled
- '1':  Device enabled (default)
